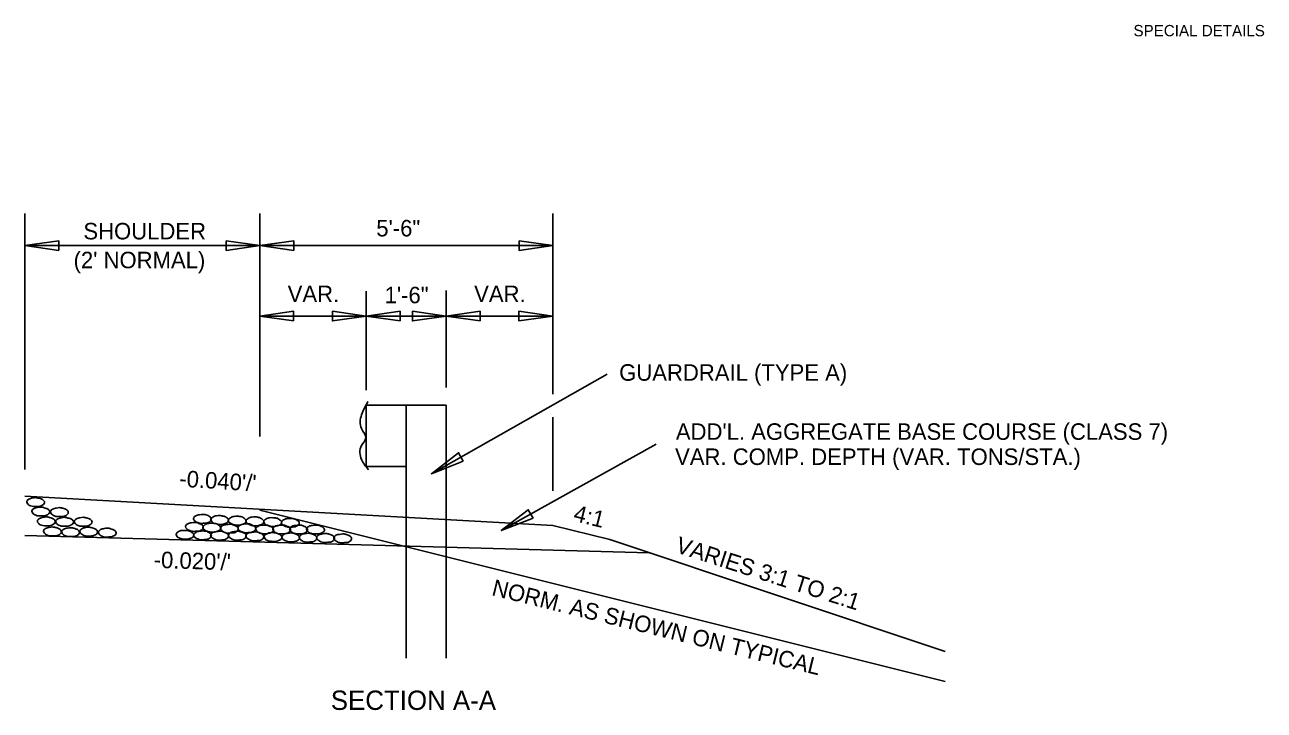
# Model space of a CAD drawing. Extents: x -149 to 1228740, y -106 to 152440.
# Drawn here: x -74.8 to -10.7, y -42.2 to -6.8 of the extents above; entities that cross this region are included whole.
import ezdxf

# ---------------------------------------------------------------- set-up
doc = ezdxf.new("R2010")
doc.units = 0
for name, color, linetype in [('R_Annotation', 7, 'Continuous'), ('R_Border', 7, 'Continuous'), ('R_Dimension', 7, 'Continuous'), ('R_Proposed Road', 7, 'Continuous'), ('R_Proposed Road_Lane', 7, 'Continuous'), ('R_Proposed Road_Shoulder', 7, 'Continuous')]:
    doc.layers.add(name, color=color, linetype=linetype)

msp = doc.modelspace()

# ---------------------------------------------------------------- linework, layer by layer
at = {"layer": 'R_Dimension'}
for p, q in [((-74.796, -29.791), (-74.796, -16.562)), ((-62.645, -28.088), (-62.645, -16.564)), ((-47.492, -25.905), (-47.492, -16.564)), ((-74.791, -18.222), (-62.645, -18.222)), ((-62.645, -18.222), (-47.492, -18.222)), ((-57.135, -25.706), (-57.135, -20.572)), ((-53.002, -25.559), (-53.002, -20.54)), ((-62.652, -21.866), (-57.142, -21.866)), ((-57.142, -21.866), (-53.009, -21.866)), ((-53.009, -21.866), (-47.498, -21.866)), ((-53.763, -30.015), (-44.678, -24.871)), ((-47.492, -30.9), (-47.492, -27.093)), ((-50.156, -32.96), (-42.146, -28.488))]:
    msp.add_line(p, q, dxfattribs=at)
for points in [[(-73.041, -18.472), (-74.791, -18.222), (-73.041, -17.972)], [(-64.389, -17.974), (-62.639, -18.224), (-64.389, -18.474)], [(-60.889, -18.474), (-62.639, -18.224), (-60.889, -17.974)], [(-49.234, -17.974), (-47.484, -18.224), (-49.234, -18.474)], [(-60.896, -22.117), (-62.646, -21.867), (-60.896, -21.617)], [(-58.885, -21.617), (-57.135, -21.867), (-58.885, -22.117)], [(-55.387, -22.117), (-57.137, -21.867), (-55.387, -21.617)], [(-54.753, -21.617), (-53.003, -21.867), (-54.753, -22.117)], [(-51.253, -22.117), (-53.003, -21.867), (-51.253, -21.617)], [(-49.241, -21.617), (-47.491, -21.867), (-49.241, -22.117)], [(-52.117, -29.37), (-53.763, -30.015), (-52.363, -28.935)], [(-48.51, -32.315), (-50.156, -32.96), (-48.756, -31.88)]]:
    msp.add_lwpolyline(points, close=True, dxfattribs=at)
at = {"layer": 'R_Proposed Road'}
msp.add_line((-74.791, -33.219), (-42.509, -34.103), dxfattribs=at)
for points in [[(-74.237, -31.251), (-74.4, -31.271), (-74.586, -31.33), (-74.68, -31.414), (-74.694, -31.473), (-74.65, -31.571), (-74.596, -31.62), (-74.488, -31.679), (-74.331, -31.713), (-74.252, -31.713), (-74.129, -31.708), (-73.997, -31.694), (-73.889, -31.649), (-73.79, -31.561), (-73.776, -31.502), (-73.805, -31.414), (-73.879, -31.355), (-73.953, -31.32), (-74.061, -31.286), (-74.134, -31.266), (-74.237, -31.251)], [(-73.971, -31.739), (-74.133, -31.759), (-74.319, -31.818), (-74.418, -31.902), (-74.432, -31.96), (-74.388, -32.059), (-74.334, -32.108), (-74.226, -32.167), (-74.069, -32.201), (-73.985, -32.201), (-73.862, -32.196), (-73.73, -32.182), (-73.627, -32.137), (-73.524, -32.049), (-73.509, -31.99), (-73.538, -31.902), (-73.612, -31.843), (-73.686, -31.808), (-73.799, -31.774), (-73.867, -31.754), (-73.971, -31.739)], [(-73.006, -31.771), (-73.168, -31.791), (-73.355, -31.85), (-73.453, -31.933), (-73.468, -31.992), (-73.424, -32.091), (-73.37, -32.14), (-73.262, -32.199), (-73.104, -32.233), (-73.021, -32.233), (-72.898, -32.228), (-72.765, -32.213), (-72.662, -32.169), (-72.559, -32.081), (-72.544, -32.022), (-72.574, -31.933), (-72.648, -31.874), (-72.721, -31.84), (-72.834, -31.806), (-72.903, -31.786), (-73.006, -31.771)], [(-73.685, -32.25), (-73.847, -32.27), (-74.034, -32.329), (-74.132, -32.412), (-74.147, -32.466), (-74.102, -32.565), (-74.048, -32.619), (-73.94, -32.678), (-73.783, -32.712), (-73.7, -32.712), (-73.577, -32.707), (-73.444, -32.692), (-73.341, -32.643), (-73.238, -32.56), (-73.223, -32.496), (-73.253, -32.407), (-73.326, -32.349), (-73.4, -32.314), (-73.513, -32.285), (-73.582, -32.26), (-73.685, -32.25)], [(-72.735, -32.272), (-72.897, -32.292), (-73.084, -32.351), (-73.182, -32.434), (-73.197, -32.489), (-73.153, -32.587), (-73.099, -32.641), (-72.991, -32.7), (-72.833, -32.734), (-72.75, -32.734), (-72.627, -32.729), (-72.494, -32.714), (-72.391, -32.665), (-72.288, -32.582), (-72.273, -32.518), (-72.303, -32.43), (-72.377, -32.371), (-72.45, -32.336), (-72.563, -32.307), (-72.632, -32.282), (-72.735, -32.272)], [(-71.779, -32.271), (-71.941, -32.29), (-72.128, -32.349), (-72.221, -32.433), (-72.236, -32.487), (-72.191, -32.585), (-72.137, -32.639), (-72.029, -32.698), (-71.872, -32.733), (-71.794, -32.733), (-71.671, -32.728), (-71.538, -32.713), (-71.43, -32.664), (-71.332, -32.58), (-71.317, -32.516), (-71.347, -32.428), (-71.42, -32.369), (-71.494, -32.335), (-71.602, -32.305), (-71.676, -32.281), (-71.779, -32.271)], [(-66.005, -32.538), (-66.177, -32.557), (-66.368, -32.606), (-66.467, -32.7), (-66.481, -32.754), (-66.432, -32.857), (-66.373, -32.901), (-66.265, -32.96), (-66.108, -32.999), (-66.029, -32.999), (-65.907, -32.99), (-65.769, -32.98), (-65.666, -32.931), (-65.577, -32.847), (-65.563, -32.783), (-65.592, -32.695), (-65.666, -32.636), (-65.735, -32.606), (-65.843, -32.562), (-65.907, -32.542), (-66.005, -32.538)], [(-65.598, -32.127), (-65.76, -32.137), (-65.956, -32.196), (-66.06, -32.29), (-66.074, -32.344), (-66.025, -32.442), (-65.966, -32.486), (-65.853, -32.54), (-65.696, -32.584), (-65.613, -32.584), (-65.495, -32.574), (-65.362, -32.56), (-65.259, -32.52), (-65.171, -32.437), (-65.156, -32.373), (-65.185, -32.285), (-65.249, -32.226), (-65.318, -32.186), (-65.426, -32.142), (-65.495, -32.127), (-65.598, -32.127)], [(-65.113, -32.579), (-65.275, -32.584), (-65.472, -32.648), (-65.57, -32.741), (-65.585, -32.795), (-65.531, -32.899), (-65.477, -32.943), (-65.369, -32.992), (-65.211, -33.031), (-65.128, -33.041), (-65.01, -33.031), (-64.877, -33.007), (-64.774, -32.967), (-64.676, -32.889), (-64.661, -32.825), (-64.691, -32.737), (-64.764, -32.678), (-64.833, -32.633), (-64.941, -32.599), (-65.01, -32.584), (-65.113, -32.579)], [(-64.718, -32.18), (-64.88, -32.19), (-65.071, -32.258), (-65.17, -32.337), (-65.184, -32.391), (-65.13, -32.494), (-65.086, -32.548), (-64.968, -32.597), (-64.821, -32.632), (-64.737, -32.642), (-64.615, -32.637), (-64.477, -32.612), (-64.379, -32.568), (-64.276, -32.489), (-64.261, -32.425), (-64.29, -32.337), (-64.364, -32.273), (-64.438, -32.239), (-64.546, -32.204), (-64.615, -32.19), (-64.718, -32.18)], [(-64.205, -32.629), (-64.367, -32.644), (-64.564, -32.698), (-64.667, -32.791), (-64.682, -32.845), (-64.628, -32.944), (-64.574, -32.988), (-64.461, -33.052), (-64.308, -33.086), (-64.225, -33.086), (-64.107, -33.076), (-63.965, -33.071), (-63.866, -33.022), (-63.773, -32.939), (-63.758, -32.875), (-63.788, -32.786), (-63.856, -32.728), (-63.93, -32.693), (-64.033, -32.659), (-64.102, -32.629), (-64.205, -32.629)], [(-63.802, -32.217), (-63.964, -32.222), (-64.16, -32.29), (-64.258, -32.379), (-64.273, -32.438), (-64.219, -32.536), (-64.165, -32.58), (-64.057, -32.629), (-63.9, -32.673), (-63.816, -32.678), (-63.698, -32.669), (-63.566, -32.644), (-63.463, -32.605), (-63.364, -32.526), (-63.35, -32.467), (-63.379, -32.379), (-63.453, -32.32), (-63.522, -32.271), (-63.63, -32.236), (-63.698, -32.222), (-63.802, -32.217)], [(-63.311, -32.606), (-63.473, -32.626), (-63.665, -32.675), (-63.763, -32.768), (-63.778, -32.822), (-63.724, -32.926), (-63.67, -32.97), (-63.562, -33.029), (-63.405, -33.068), (-63.326, -33.068), (-63.203, -33.058), (-63.071, -33.048), (-62.962, -32.999), (-62.869, -32.916), (-62.854, -32.852), (-62.884, -32.764), (-62.958, -32.705), (-63.031, -32.675), (-63.134, -32.626), (-63.208, -32.611), (-63.311, -32.606)], [(-62.885, -32.253), (-63.048, -32.258), (-63.244, -32.327), (-63.342, -32.416), (-63.357, -32.475), (-63.303, -32.573), (-63.249, -32.617), (-63.141, -32.666), (-62.984, -32.71), (-62.9, -32.715), (-62.782, -32.705), (-62.65, -32.681), (-62.547, -32.642), (-62.448, -32.563), (-62.434, -32.504), (-62.463, -32.416), (-62.537, -32.357), (-62.605, -32.308), (-62.714, -32.273), (-62.782, -32.258), (-62.885, -32.253)], [(-62.383, -32.67), (-62.545, -32.675), (-62.741, -32.739), (-62.84, -32.832), (-62.854, -32.886), (-62.8, -32.99), (-62.746, -33.034), (-62.638, -33.083), (-62.481, -33.122), (-62.398, -33.132), (-62.28, -33.122), (-62.147, -33.098), (-62.044, -33.058), (-61.946, -32.98), (-61.931, -32.916), (-61.96, -32.827), (-62.034, -32.768), (-62.103, -32.724), (-62.211, -32.69), (-62.28, -32.675), (-62.383, -32.67)], [(-61.969, -32.29), (-62.131, -32.295), (-62.328, -32.364), (-62.426, -32.452), (-62.441, -32.511), (-62.387, -32.61), (-62.333, -32.654), (-62.225, -32.703), (-62.068, -32.747), (-61.984, -32.752), (-61.866, -32.742), (-61.734, -32.718), (-61.63, -32.678), (-61.532, -32.6), (-61.517, -32.541), (-61.547, -32.452), (-61.621, -32.393), (-61.689, -32.344), (-61.797, -32.31), (-61.866, -32.295), (-61.969, -32.29)], [(-61.508, -32.67), (-61.67, -32.69), (-61.861, -32.739), (-61.96, -32.832), (-61.974, -32.886), (-61.92, -32.99), (-61.866, -33.034), (-61.758, -33.093), (-61.601, -33.132), (-61.522, -33.132), (-61.4, -33.122), (-61.267, -33.112), (-61.159, -33.063), (-61.066, -32.98), (-61.051, -32.916), (-61.08, -32.827), (-61.154, -32.768), (-61.228, -32.739), (-61.331, -32.69), (-61.404, -32.675), (-61.508, -32.67)], [(-61.053, -32.327), (-61.215, -32.332), (-61.412, -32.401), (-61.51, -32.489), (-61.525, -32.548), (-61.471, -32.646), (-61.417, -32.691), (-61.309, -32.74), (-61.151, -32.784), (-61.068, -32.789), (-60.95, -32.779), (-60.817, -32.755), (-60.714, -32.715), (-60.616, -32.637), (-60.601, -32.578), (-60.631, -32.489), (-60.704, -32.43), (-60.773, -32.381), (-60.881, -32.347), (-60.95, -32.332), (-61.053, -32.327)], [(-60.632, -32.67), (-60.795, -32.69), (-60.986, -32.739), (-61.084, -32.832), (-61.099, -32.886), (-61.045, -32.99), (-60.991, -33.034), (-60.883, -33.093), (-60.726, -33.132), (-60.647, -33.132), (-60.524, -33.122), (-60.392, -33.112), (-60.284, -33.063), (-60.19, -32.98), (-60.176, -32.916), (-60.205, -32.827), (-60.279, -32.768), (-60.352, -32.739), (-60.456, -32.69), (-60.529, -32.675), (-60.632, -32.67)], [(-59.757, -32.67), (-59.919, -32.69), (-60.111, -32.739), (-60.209, -32.832), (-60.224, -32.886), (-60.17, -32.99), (-60.116, -33.034), (-60.008, -33.093), (-59.851, -33.132), (-59.772, -33.132), (-59.649, -33.122), (-59.517, -33.112), (-59.408, -33.063), (-59.315, -32.98), (-59.3, -32.916), (-59.33, -32.827), (-59.404, -32.768), (-59.477, -32.739), (-59.58, -32.69), (-59.654, -32.675), (-59.757, -32.67)], [(-73.37, -32.771), (-73.532, -32.791), (-73.718, -32.85), (-73.812, -32.933), (-73.826, -32.992), (-73.782, -33.09), (-73.728, -33.139), (-73.62, -33.198), (-73.463, -33.233), (-73.384, -33.233), (-73.262, -33.228), (-73.129, -33.213), (-73.021, -33.169), (-72.923, -33.08), (-72.908, -33.022), (-72.937, -32.933), (-73.011, -32.874), (-73.085, -32.84), (-73.193, -32.805), (-73.266, -32.786), (-73.37, -32.771)], [(-72.431, -32.807), (-72.593, -32.827), (-72.78, -32.886), (-72.873, -32.969), (-72.888, -33.028), (-72.844, -33.126), (-72.79, -33.175), (-72.682, -33.234), (-72.525, -33.269), (-72.446, -33.269), (-72.323, -33.264), (-72.191, -33.249), (-72.083, -33.205), (-71.984, -33.116), (-71.97, -33.058), (-71.999, -32.969), (-72.073, -32.91), (-72.146, -32.876), (-72.255, -32.841), (-72.328, -32.822), (-72.431, -32.807)], [(-71.496, -32.781), (-71.658, -32.8), (-71.844, -32.859), (-71.938, -32.943), (-71.952, -32.997), (-71.908, -33.095), (-71.854, -33.149), (-71.746, -33.208), (-71.589, -33.243), (-71.51, -33.243), (-71.388, -33.238), (-71.255, -33.223), (-71.147, -33.174), (-71.049, -33.09), (-71.034, -33.026), (-71.063, -32.938), (-71.137, -32.879), (-71.211, -32.845), (-71.319, -32.815), (-71.392, -32.791), (-71.496, -32.781)], [(-70.533, -32.832), (-70.695, -32.851), (-70.882, -32.91), (-70.975, -32.994), (-70.99, -33.048), (-70.945, -33.146), (-70.891, -33.2), (-70.783, -33.259), (-70.626, -33.293), (-70.548, -33.293), (-70.425, -33.288), (-70.292, -33.274), (-70.184, -33.225), (-70.086, -33.141), (-70.071, -33.077), (-70.101, -32.989), (-70.174, -32.93), (-70.248, -32.895), (-70.356, -32.866), (-70.43, -32.841), (-70.533, -32.832)], [(-66.506, -32.946), (-66.668, -32.951), (-66.864, -33.02), (-66.958, -33.108), (-66.972, -33.167), (-66.923, -33.265), (-66.864, -33.31), (-66.761, -33.359), (-66.599, -33.403), (-66.521, -33.408), (-66.398, -33.398), (-66.265, -33.373), (-66.162, -33.334), (-66.069, -33.256), (-66.054, -33.197), (-66.083, -33.108), (-66.157, -33.049), (-66.226, -33), (-66.334, -32.966), (-66.403, -32.951), (-66.506, -32.946)], [(-65.597, -32.975), (-65.759, -32.99), (-65.956, -33.048), (-66.049, -33.137), (-66.064, -33.196), (-66.015, -33.294), (-65.965, -33.338), (-65.852, -33.387), (-65.7, -33.437), (-65.617, -33.437), (-65.494, -33.427), (-65.356, -33.407), (-65.258, -33.373), (-65.16, -33.284), (-65.145, -33.225), (-65.175, -33.137), (-65.248, -33.078), (-65.322, -33.034), (-65.425, -32.994), (-65.494, -32.98), (-65.597, -32.975)], [(-64.714, -32.988), (-64.876, -33.008), (-65.072, -33.062), (-65.171, -33.15), (-65.185, -33.209), (-65.131, -33.307), (-65.077, -33.351), (-64.969, -33.41), (-64.817, -33.45), (-64.733, -33.45), (-64.611, -33.44), (-64.478, -33.43), (-64.375, -33.386), (-64.276, -33.297), (-64.262, -33.238), (-64.291, -33.15), (-64.365, -33.091), (-64.439, -33.057), (-64.547, -33.017), (-64.611, -32.993), (-64.714, -32.988)], [(-63.789, -32.987), (-63.956, -33.007), (-64.153, -33.061), (-64.251, -33.149), (-64.266, -33.208), (-64.212, -33.306), (-64.158, -33.351), (-64.045, -33.414), (-63.893, -33.449), (-63.814, -33.449), (-63.691, -33.444), (-63.554, -33.429), (-63.45, -33.385), (-63.357, -33.297), (-63.342, -33.238), (-63.372, -33.149), (-63.445, -33.09), (-63.519, -33.056), (-63.622, -33.021), (-63.686, -33.002), (-63.789, -32.987)], [(-62.884, -33.024), (-63.056, -33.044), (-63.242, -33.093), (-63.346, -33.186), (-63.36, -33.24), (-63.306, -33.343), (-63.252, -33.387), (-63.139, -33.446), (-62.987, -33.486), (-62.908, -33.486), (-62.786, -33.476), (-62.643, -33.466), (-62.545, -33.417), (-62.452, -33.333), (-62.437, -33.27), (-62.466, -33.181), (-62.54, -33.122), (-62.609, -33.093), (-62.717, -33.053), (-62.781, -33.029), (-62.884, -33.024)], [(-61.958, -33.062), (-62.12, -33.071), (-62.312, -33.14), (-62.41, -33.219), (-62.425, -33.273), (-62.371, -33.376), (-62.326, -33.43), (-62.208, -33.479), (-62.061, -33.513), (-61.978, -33.523), (-61.855, -33.518), (-61.717, -33.494), (-61.619, -33.45), (-61.516, -33.371), (-61.501, -33.307), (-61.531, -33.219), (-61.604, -33.155), (-61.678, -33.12), (-61.786, -33.086), (-61.855, -33.071), (-61.958, -33.062)], [(-61.034, -33.08), (-61.196, -33.095), (-61.393, -33.154), (-61.486, -33.242), (-61.501, -33.301), (-61.452, -33.4), (-61.403, -33.444), (-61.29, -33.493), (-61.138, -33.542), (-61.054, -33.542), (-60.931, -33.532), (-60.794, -33.513), (-60.695, -33.478), (-60.597, -33.39), (-60.582, -33.331), (-60.612, -33.242), (-60.686, -33.184), (-60.759, -33.139), (-60.862, -33.1), (-60.931, -33.085), (-61.034, -33.08)], [(-60.138, -33.095), (-60.3, -33.115), (-60.497, -33.169), (-60.595, -33.257), (-60.609, -33.316), (-60.555, -33.414), (-60.501, -33.459), (-60.393, -33.518), (-60.241, -33.557), (-60.158, -33.557), (-60.035, -33.547), (-59.902, -33.537), (-59.799, -33.493), (-59.701, -33.405), (-59.686, -33.346), (-59.715, -33.257), (-59.789, -33.198), (-59.863, -33.164), (-59.971, -33.125), (-60.035, -33.1), (-60.138, -33.095)], [(-59.228, -33.107), (-59.395, -33.127), (-59.592, -33.181), (-59.69, -33.27), (-59.705, -33.328), (-59.651, -33.427), (-59.597, -33.471), (-59.484, -33.535), (-59.331, -33.569), (-59.253, -33.569), (-59.13, -33.564), (-58.993, -33.55), (-58.889, -33.505), (-58.796, -33.417), (-58.781, -33.358), (-58.811, -33.27), (-58.884, -33.211), (-58.958, -33.176), (-59.061, -33.142), (-59.125, -33.122), (-59.228, -33.107)], [(-58.342, -33.133), (-58.514, -33.152), (-58.705, -33.202), (-58.803, -33.295), (-58.818, -33.349), (-58.764, -33.447), (-58.71, -33.491), (-58.602, -33.55), (-58.445, -33.595), (-58.366, -33.595), (-58.243, -33.58), (-58.106, -33.575), (-58.003, -33.526), (-57.909, -33.442), (-57.895, -33.378), (-57.924, -33.29), (-57.998, -33.231), (-58.071, -33.197), (-58.175, -33.157), (-58.243, -33.138), (-58.342, -33.133)]]:
    msp.add_spline(points, degree=3, dxfattribs=at)
at = {"layer": 'R_Proposed Road_Lane'}
for p, q in [((-74.796, -31.17), (-47.486, -32.689)), ((-47.486, -32.689), (-44.54, -33.426)), ((-44.54, -33.426), (-27.194, -39.215))]:
    msp.add_line(p, q, dxfattribs=at)
at = {"layer": 'R_Proposed Road_Shoulder'}
for p, q in [((-57.135, -26.465), (-57.135, -29.643)), ((-57.135, -26.465), (-53.002, -26.465)), ((-55.068, -26.465), (-55.068, -39.546)), ((-53.002, -26.465), (-53.002, -39.558)), ((-57.135, -29.643), (-55.068, -29.643)), ((-62.639, -31.894), (-27.194, -40.755))]:
    msp.add_line(p, q, dxfattribs=at)
msp.add_spline([(-57.049, -26.287), (-57.383, -26.977), (-57.383, -27.687), (-57.159, -28.169), (-57.383, -28.562), (-57.383, -29.286), (-57.029, -29.809)], degree=3, dxfattribs=at)

# ---------------------------------------------------------------- texts
at = {"layer": 'R_Annotation'}
for s, height, p in [('SHOULDER ', 0.8533, (-71.765, -17.902)), ('5\'-6"', 0.8533, (-56.617, -17.749)), ("(2' NORMAL)", 0.85327, (-72.272, -19.395)), ('VAR.', 0.8533, (-61.2, -21.146)), ('1\'-6"', 0.8533, (-56.186, -21.205)), ('VAR.', 0.8533, (-51.557, -21.146)), ('GUARDRAIL (TYPE A)', 0.85327, (-44.057, -25.21)), ("ADD'L. AGGREGATE BASE COURSE (CLASS 7)", 0.85327, (-41.125, -28.265)), ('VAR. COMP. DEPTH (VAR. TONS/STA.)', 0.85327, (-41.165, -29.565)), ('SECTION A-A', 1, (-58.971, -42.23))]:
    msp.add_text(s, height=height, dxfattribs=at).set_placement(p)
for s, height, rotation, p in [("-0.040'/'", 0.8533, 356.40267, (-66.825, -30.683)), ('4:1', 0.8533, 345.95866, (-46.469, -32.444)), ('VARIES 3:1 TO 2:1', 0.85327, 342.20007, (-41.19, -34.067)), ("-0.020'/'", 0.8533, 358.0742, (-68.14, -34.88)), ('NORM. AS SHOWN ON TYPICAL', 0.85327, 346.22108, (-50.692, -36.292))]:
    msp.add_text(s, height=height, rotation=rotation, dxfattribs=at).set_placement(p)
at = {"layer": 'R_Border'}
msp.add_text('SPECIAL DETAILS', height=0.5862, dxfattribs=at).set_placement((-17.46, -7.401))

doc.saveas('drawing.dxf')
